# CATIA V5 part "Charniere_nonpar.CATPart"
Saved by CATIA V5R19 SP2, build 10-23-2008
Part number: Charniere
Bounding box of the stored display mesh (mm): x -7.954 to 7.954, y -30 to 26, z -18.5 to 18.5
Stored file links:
  F:\Projet CAO\pièces et assemblages\mécanisme 577\577-SaintAime\577-SaintAime\Charniere_nonpar.CATPart
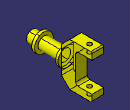
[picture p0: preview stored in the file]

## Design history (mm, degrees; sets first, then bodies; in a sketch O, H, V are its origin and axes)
Body1 (main body)
  Sketch1 on yz-plane, origin (0, 0, 0), H (0, 1, 0), V (0, 0, 1)
    line L1 (-30, 5) -> (-22.5, 5)
    line L2 (-22.5, 5) -> (-22.5, 8)
    line L3 (-22.5, 8) -> (-20, 8)
    line L4 (-20, 8) -> (-20, 5)
    point P5 (-20, 5)
    line L5 (-20, 5) -> (-2, 5)
    line L6 (-2, 5) -> (-2, 8)
    point P7 (-2, 8)
    line L7 (-2, 8) -> (0, 8)
    point P8 (0, 8)
    line L8 (0, 8) -> (0, 0)
    line L9 (0, 0) -> (-30, 0)
    line L10 (-30, 0) -> (-30, 5)
    length L10 = 5
    distance L3 H = 8
    distance L2 L4 = 2.5
    distance L6 L8 = 2
    distance L4 L6 = 18
    distance L2 L10 = 7.5
    horizontal: L1 H, L3 H, L5 H, L7 H, L9 H
    vertical: L2 V, L4 V, L6 V, L8 V, L10 V
    coincidence: P5 L1, P7 L3, P8 V
  Shaft1: profile Sketch1, axis Sketch1.L9, angle 360
  Sketch2 on yz-plane, origin (0, 0, 0), H (0, 1, 0), V (0, 0, 1)
    projected line E1 (0, 8) -> (0, -8) from edge [face of Shaft1 from Sketch1.L7 | face of Shaft1 from Sketch1.L8]
    line L1 (0, 8) -> (0, 11.4289)
    line L2 (0, 11.4289) -> (7.0711, 18.5)
    line L3 (7.0711, 18.5) -> (26, 18.5)
    line L4 (26, 18.5) -> (26, 12.5)
    line L5 (26, 12.5) -> (14, 12.5)
    line L6 (12, 10.5) -> (12, -10.5)
    line L7 (14, -12.5) -> (26, -12.5)
    point P7 (26, -12.5)
    line L8 (26, -12.5) -> (26, -18.5)
    line L9 (26, -18.5) -> (7.0711, -18.5)
    line L10 (7.0711, -18.5) -> (0, -11.4289)
    point P10 (0, -11.4289)
    line L11 (0, -11.4289) -> (0, -8)
    arc A1 centre (14, 10.5) radius 2 from (12, 10.5) to (14, 12.5) cw
    arc A2 centre (14, -10.5) radius 2 from (14, -12.5) to (12, -10.5) cw
    distance L6 E1 = 12
    distance L5 L7 = 25
    distance L3 L5 = 6
    length L2 = 10
    distance L4 L6 = 14
    angle L10 E1 = 45
    radius A1 = 2
    radius A2 = 2
    vertical: L1 V, L4 V, L6 V, L8 V, L11 V
    horizontal: L3 H, L5 H, L7 H, L9 H
    coincidence: P7 L4, P10 V
    symmetry: L3 L9 H, L5 L7 H, L10 L2 H
    tangency: A1 L6, A1 L5, A2 L7, A2 L6
  Pad1: profile Sketch2, direction (1, 0, 0), length 5, mirrored extent
  Sketch3 on face of Pad1 from Sketch2.L3, origin (0, 0, 18.5), H (1, 0, 0), V (0, 1, 0)
    circle A1 centre (0, 19) radius 2
    point P1 (0, 19)
    reference projected line E1 (5, 12) -> (-5, 12) from face of Pad1 from Sketch2.L6
    reference projected line E2 (-5, 26) -> (5, 26) from edge [face of Pad1 from Sketch2.L3 | face of Pad1 from Sketch2.L4]
    radius A1 = 2
    coincidence: P1 V
    equidistance: E1 E2 P1
  Pocket1: profile Sketch3, direction (0, 0, -1), through (limit type 3)
  Fillet1: radius 1, on edge [face of Pad1 from Sketch2.L3 | face of Pad1 from Sketch2.L4]; edge [face of Pad1 from Sketch2.L8 | face of Pad1 from Sketch2.L9]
